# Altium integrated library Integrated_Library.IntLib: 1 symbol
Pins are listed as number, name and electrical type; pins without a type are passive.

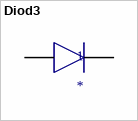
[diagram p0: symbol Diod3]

## Diod3
designator 1
footprint PCBComponent_1
pins: 1, 2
